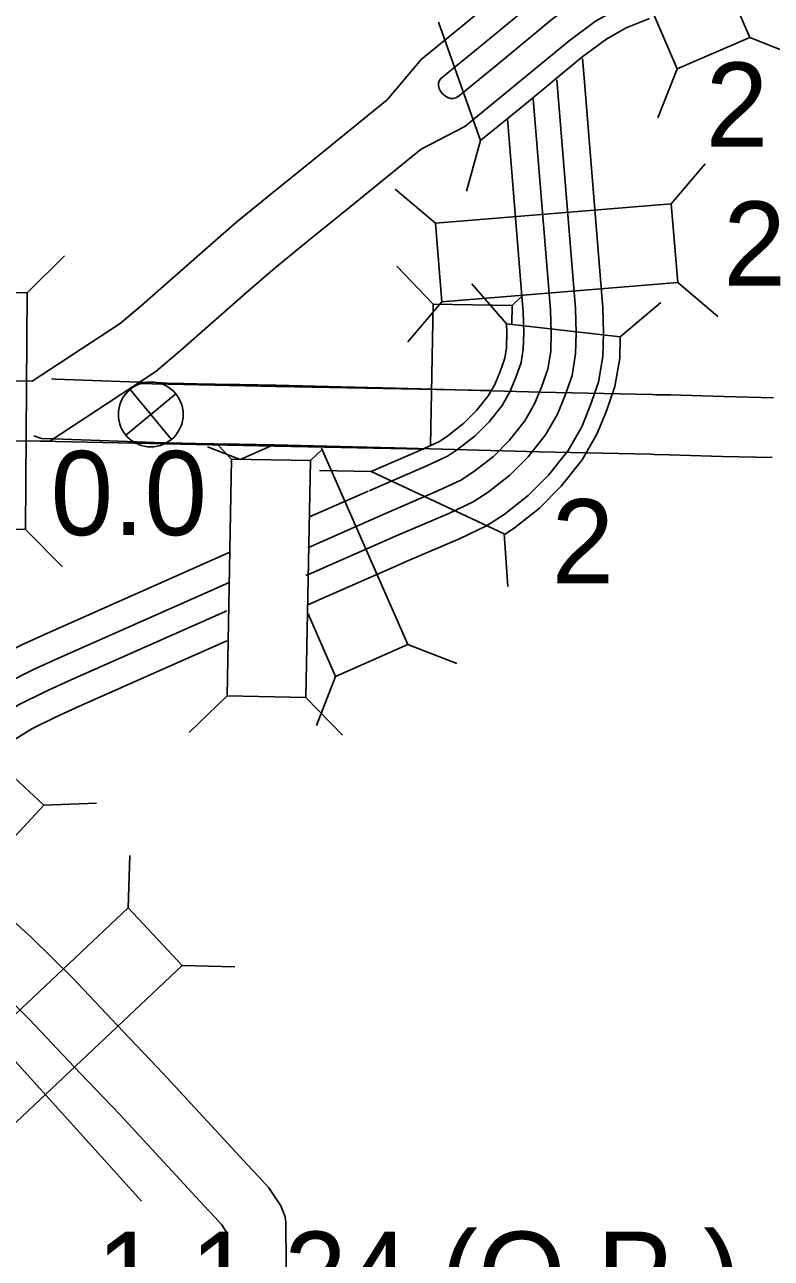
# Model space of a CAD drawing. Extents: x -939622 to -934245, y 1383184 to 1385301.
# Drawn here: x -936404.69 to -936393.44, y 1384599.72 to 1384618.29 of the extents above; entities that cross this region are included whole.
import ezdxf

# ---------------------------------------------------------------- set-up
doc = ezdxf.new("R2010")
doc.units = 0
for name, color, linetype in [('Level 10', 7, 'Continuous'), ('Level 15', 7, 'Continuous'), ('Level 19', 7, 'Continuous'), ('Level 20', 7, 'Continuous'), ('Level 25', 7, 'Continuous'), ('Level 26', 7, 'Continuous')]:
    doc.layers.add(name, color=color, linetype=linetype)

msp = doc.modelspace()

# ---------------------------------------------------------------- linework, layer by layer
at = {"layer": 'Level 10'}
for p, q in [((-936396.919, 1384612.756), (-936399.095, 1384612.817)), ((-936396.944, 1384611.857), (-936399.12, 1384611.918))]:
    msp.add_line(p, q, dxfattribs=at)
for points in [[(-936399.097, 1384612.817), (-936399.723, 1384612.832), (-936400.907, 1384612.863), (-936401.447, 1384612.871), (-936401.821, 1384612.877), (-936401.891, 1384612.878), (-936402.292, 1384612.887), (-936402.547, 1384612.892), (-936402.702, 1384612.899), (-936402.968, 1384612.908), (-936403.807, 1384612.938), (-936404.227, 1384612.952), (-936404.274, 1384612.954), (-936404.266, 1384612.951)], [(-936402.995, 1384612.887), (-936400.903, 1384612.842), (-936397.672, 1384612.78)], [(-936393.41, 1384612.672), (-936394.162, 1384612.689), (-936394.961, 1384612.713), (-936395.176, 1384612.717), (-936395.232, 1384612.719), (-936395.967, 1384612.735), (-936396.921, 1384612.757)], [(-936399.119, 1384611.918), (-936399.745, 1384611.933), (-936400.925, 1384611.963), (-936401.46, 1384611.971), (-936401.835, 1384611.977), (-936401.909, 1384611.978), (-936402.312, 1384611.987), (-936402.575, 1384611.993), (-936402.735, 1384611.999), (-936403, 1384612.008), (-936403.839, 1384612.038), (-936404.258, 1384612.053), (-936404.436, 1384612.059), (-936404.552, 1384612.098)], [(-936404.453, 1384612.018), (-936400.921, 1384611.942), (-936398.682, 1384611.899)], [(-936393.43, 1384611.772), (-936394.186, 1384611.789), (-936394.982, 1384611.814), (-936395.202, 1384611.817), (-936395.26, 1384611.82), (-936395.987, 1384611.835), (-936396.942, 1384611.857)], [(-936400.83, 1384600.505), (-936401.009, 1384600.778), (-936401.168, 1384600.95), (-936401.331, 1384601.123), (-936402.601, 1384602.498), (-936403.205, 1384603.13), (-936403.969, 1384603.94), (-936404.585, 1384604.548), (-936405.293, 1384605.182), (-936406.201, 1384605.924), (-936406.36, 1384606.054)], [(-936401.657, 1384600.125), (-936401.72, 1384600.222), (-936401.826, 1384600.336), (-936401.989, 1384600.51), (-936403.257, 1384601.882), (-936403.858, 1384602.51), (-936404.613, 1384603.311), (-936405.202, 1384603.892), (-936405.879, 1384604.498), (-936406.77, 1384605.228), (-936407.033, 1384605.442)], [(-936400.83, 1384600.505), (-936400.801, 1384600.43), (-936400.766, 1384600.339), (-936400.757, 1384600.262)], [(-936400.851, 1384588.552), (-936400.855, 1384588.625), (-936400.726, 1384596.507), (-936400.757, 1384600.262)], [(-936401.75, 1384588.506), (-936401.756, 1384588.609), (-936401.626, 1384596.511), (-936401.656, 1384600.127)]]:
    msp.add_lwpolyline(points, dxfattribs=at)
at = {"layer": 'Level 15'}
for points in [[(-936398.42, 1384617.477), (-936397.83, 1384617.959), (-936396.976, 1384618.664), (-936396.522, 1384619.001), (-936396.107, 1384619.235), (-936395.184, 1384619.599), (-936394.18, 1384620.033), (-936391.147, 1384621.405), (-936387.048, 1384623.231), (-936384.039, 1384624.587), (-936381.834, 1384625.586), (-936379.396, 1384626.693), (-936377.142, 1384627.69), (-936375.476, 1384628.466), (-936373.359, 1384629.459), (-936371.298, 1384630.427), (-936369.171, 1384631.443), (-936367.666, 1384632.201), (-936365.853, 1384633.102)], [(-936398.164, 1384617.202), (-936397.592, 1384617.669), (-936396.744, 1384618.369), (-936396.317, 1384618.686), (-936395.945, 1384618.896), (-936395.041, 1384619.252), (-936394.028, 1384619.69), (-936390.994, 1384621.062), (-936386.895, 1384622.889), (-936383.884, 1384624.245), (-936381.679, 1384625.245), (-936379.243, 1384626.351), (-936376.987, 1384627.348), (-936375.318, 1384628.126), (-936373.2, 1384629.119), (-936371.138, 1384630.088), (-936369.006, 1384631.107), (-936367.499, 1384631.865), (-936365.686, 1384632.766)], [(-936398.058, 1384616.756), (-936397.33, 1384617.35), (-936396.49, 1384618.044), (-936396.092, 1384618.339), (-936395.767, 1384618.522), (-936394.883, 1384618.871), (-936393.862, 1384619.313), (-936390.825, 1384620.686), (-936386.726, 1384622.512), (-936383.714, 1384623.869), (-936381.509, 1384624.869), (-936379.074, 1384625.975), (-936376.816, 1384626.973), (-936375.143, 1384627.752), (-936373.024, 1384628.746), (-936370.961, 1384629.716), (-936368.824, 1384630.736), (-936367.314, 1384631.496), (-936365.502, 1384632.397)], [(-936398.719, 1384617.765), (-936398.092, 1384618.277), (-936397.23, 1384618.989), (-936396.747, 1384619.348), (-936396.285, 1384619.608), (-936395.835, 1384619.786)], [(-936399.23, 1384617.155), (-936398.719, 1384617.765)], [(-936402.928, 1384614.062), (-936401.889, 1384614.974), (-936401.495, 1384615.318), (-936400.983, 1384615.734), (-936400.36, 1384616.24), (-936399.438, 1384616.985), (-936399.23, 1384617.155)], [(-936398.716, 1384616.412), (-936398.058, 1384616.756)], [(-936402.345, 1384613.376), (-936401.305, 1384614.289), (-936400.915, 1384614.629), (-936400.415, 1384615.036), (-936399.794, 1384615.541), (-936398.871, 1384616.286), (-936398.716, 1384616.412)], [(-936409.262, 1384612.951), (-936404.576, 1384612.919), (-936403.251, 1384613.788), (-936402.928, 1384614.062)], [(-936408.925, 1384612.048), (-936404.31, 1384612.017), (-936402.711, 1384613.066), (-936402.345, 1384613.376)]]:
    msp.add_lwpolyline(points, dxfattribs=at)
msp.add_ellipse((-936398.294, 1384617.341), major_axis=(-0.128, 0.137), ratio=0.733949, start_param=0, end_param=3.141593, dxfattribs=at)
at = {"layer": 'Level 19'}
for points in [[(-936395.991, 1384614.144), (-936396.27, 1384617.547), (-936396.289, 1384617.78)], [(-936400.453, 1384609.993), (-936400.367, 1384610.031), (-936399.106, 1384610.585), (-936398.301, 1384610.931), (-936397.934, 1384611.102), (-936397.708, 1384611.25), (-936397.38, 1384611.508), (-936397.106, 1384611.783), (-936396.844, 1384612.111), (-936396.672, 1384612.414), (-936396.556, 1384612.695), (-936396.446, 1384613.007), (-936396.393, 1384613.331), (-936396.385, 1384613.649), (-936396.394, 1384614.013), (-936396.677, 1384617.456)], [(-936400.426, 1384610.414), (-936399.255, 1384610.929), (-936398.455, 1384611.273), (-936398.118, 1384611.431), (-936397.927, 1384611.555), (-936397.63, 1384611.789), (-936397.386, 1384612.033), (-936397.156, 1384612.322), (-936397.009, 1384612.579), (-936396.907, 1384612.829), (-936396.811, 1384613.101), (-936396.767, 1384613.366), (-936396.76, 1384613.649), (-936396.769, 1384613.993), (-936397.029, 1384617.169)], [(-936397.195, 1384614.141), (-936397.418, 1384616.869)], [(-936399.502, 1384611.271), (-936399.42, 1384611.307), (-936398.623, 1384611.649), (-936398.319, 1384611.792), (-936398.168, 1384611.891), (-936397.904, 1384612.097), (-936397.695, 1384612.308), (-936397.498, 1384612.554), (-936397.381, 1384612.76), (-936397.292, 1384612.975), (-936397.212, 1384613.204), (-936397.179, 1384613.405), (-936397.173, 1384613.649), (-936397.181, 1384613.972), (-936397.195, 1384614.141)], [(-936399.099, 1384610.137), (-936398.941, 1384610.207), (-936398.132, 1384610.554), (-936397.733, 1384610.741), (-936397.467, 1384610.915), (-936397.105, 1384611.199), (-936396.798, 1384611.508), (-936396.502, 1384611.878), (-936396.3, 1384612.233), (-936396.171, 1384612.548), (-936396.045, 1384612.904), (-936395.981, 1384613.292), (-936395.973, 1384613.649), (-936395.982, 1384614.035), (-936395.991, 1384614.143)], [(-936400.397, 1384610.878), (-936399.515, 1384611.266)], [(-936407.557, 1384606.775), (-936406.62, 1384607.781), (-936406.135, 1384608.13), (-936405.629, 1384608.45), (-936405.164, 1384608.737), (-936404.731, 1384608.951), (-936404.346, 1384609.127), (-936401.607, 1384610.342)], [(-936400.435, 1384609.549), (-936400.2, 1384609.653), (-936399.099, 1384610.137)], [(-936407.273, 1384606.474), (-936406.347, 1384607.47), (-936405.904, 1384607.787), (-936405.41, 1384608.1), (-936404.964, 1384608.376), (-936404.554, 1384608.579), (-936404.177, 1384608.751), (-936401.621, 1384609.884)], [(-936407.004, 1384606.213), (-936406.098, 1384607.187), (-936405.694, 1384607.476), (-936405.211, 1384607.783), (-936404.782, 1384608.048), (-936404.392, 1384608.24), (-936404.023, 1384608.409), (-936401.646, 1384609.463)], [(-936406.721, 1384605.911), (-936405.824, 1384606.876), (-936405.464, 1384607.134), (-936404.992, 1384607.433), (-936404.581, 1384607.686), (-936404.215, 1384607.868), (-936403.854, 1384608.033), (-936401.643, 1384609.014)]]:
    msp.add_lwpolyline(points, dxfattribs=at)
at = {"layer": 'Level 20'}
for p, q in [((-936393.77, 1384618.095), (-936395.185, 1384621.366)), ((-936396.275, 1384620.895), (-936394.86, 1384617.623)), ((-936398.456, 1384618.327), (-936397.823, 1384616.544)), ((-936394.86, 1384617.623), (-936393.77, 1384618.095)), ((-936393.77, 1384618.095), (-936393.034, 1384617.803)), ((-936394.86, 1384617.623), (-936395.152, 1384616.887)), ((-936398.035, 1384615.781), (-936397.823, 1384616.544)), ((-936394.951, 1384615.591), (-936394.439, 1384616.195)), ((-936398.503, 1384615.3), (-936399.107, 1384615.812)), ((-936394.951, 1384615.591), (-936398.503, 1384615.3)), ((-936394.854, 1384614.407), (-936394.951, 1384615.591)), ((-936398.503, 1384615.3), (-936398.406, 1384614.116)), ((-936404.651, 1384614.251), (-936404.087, 1384614.808)), ((-936398.535, 1384614.081), (-936399.084, 1384614.652)), ((-936398.406, 1384614.116), (-936394.854, 1384614.407)), ((-936397.953, 1384614.386), (-936397.431, 1384613.785)), ((-936394.854, 1384614.407), (-936394.25, 1384613.895)), ((-936398.406, 1384614.116), (-936398.918, 1384613.512)), ((-936397.347, 1384614.058), (-936397.191, 1384614.208)), ((-936395.11, 1384614.103), (-936395.72, 1384613.588)), ((-936398.535, 1384614.081), (-936398.576, 1384611.952)), ((-936397.347, 1384614.058), (-936398.535, 1384614.081)), ((-936397.353, 1384613.774), (-936397.347, 1384614.058)), ((-936395.72, 1384613.588), (-936397.431, 1384613.785)), ((-936401.441, 1384611.74), (-936401.934, 1384611.932)), ((-936401.573, 1384611.746), (-936401.779, 1384611.96)), ((-936400.985, 1384611.94), (-936401.441, 1384611.74)), ((-936400.385, 1384611.724), (-936400.209, 1384611.893)), ((-936398.919, 1384608.956), (-936400.219, 1384611.912)), ((-936401.573, 1384611.746), (-936401.64, 1384608.183)), ((-936400.385, 1384611.724), (-936401.573, 1384611.746)), ((-936400.452, 1384608.16), (-936400.385, 1384611.724)), ((-936400.248, 1384611.577), (-936399.469, 1384611.563)), ((-936399.469, 1384611.563), (-936397.467, 1384610.62)), ((-936404.675, 1384610.687), (-936404.119, 1384610.124)), ((-936397.41, 1384609.828), (-936397.467, 1384610.62)), ((-936400.421, 1384609.42), (-936400.006, 1384608.477)), ((-936400.006, 1384608.477), (-936398.919, 1384608.956)), ((-936398.919, 1384608.956), (-936398.181, 1384608.668)), ((-936400.006, 1384608.477), (-936400.294, 1384607.739)), ((-936401.64, 1384608.183), (-936402.211, 1384607.633)), ((-936401.64, 1384608.183), (-936400.452, 1384608.16)), ((-936400.452, 1384608.16), (-936399.903, 1384607.59)), ((-936404.398, 1384606.539), (-936403.607, 1384606.568)), ((-936403.129, 1384604.991), (-936403.105, 1384605.782)), ((-936402.314, 1384604.126), (-936401.522, 1384604.102))]:
    msp.add_line(p, q, dxfattribs=at)
for points in [[(-936397.823, 1384616.544), (-936397.132, 1384617.108), (-936396.297, 1384617.797), (-936395.921, 1384618.076), (-936395.632, 1384618.239), (-936395.28, 1384618.378)], [(-936399.469, 1384611.563), (-936398.728, 1384611.882), (-936398.443, 1384612.015), (-936398.316, 1384612.098), (-936398.074, 1384612.288), (-936397.885, 1384612.478), (-936397.709, 1384612.698), (-936397.61, 1384612.872), (-936397.53, 1384613.066), (-936397.46, 1384613.267), (-936397.433, 1384613.429), (-936397.428, 1384613.649), (-936397.431, 1384613.785)], [(-936397.463, 1384610.614), (-936397.319, 1384610.709), (-936396.937, 1384611.009), (-936396.608, 1384611.339), (-936396.291, 1384611.736), (-936396.072, 1384612.122), (-936395.934, 1384612.458), (-936395.799, 1384612.841), (-936395.728, 1384613.268), (-936395.72, 1384613.588)]]:
    msp.add_lwpolyline(points, dxfattribs=at)
for points in [[(-936405.839, 1384614.259), (-936405.863, 1384610.696), (-936404.675, 1384610.687), (-936404.651, 1384614.251)], [(-936407.817, 1384608.097), (-936405.207, 1384605.669), (-936404.398, 1384606.539), (-936407.008, 1384608.967)], [(-936404.908, 1384601.682), (-936402.314, 1384604.126), (-936403.129, 1384604.991), (-936405.723, 1384602.547)]]:
    msp.add_lwpolyline(points, close=True, dxfattribs=at)
at = {"layer": 'Level 25'}
msp.add_line((-936407.156, 1384605.26), (-936402.93, 1384600.577), dxfattribs=at)
at = {"layer": 'Level 26'}
for p, q in [((-936403.166, 1384612.108), (-936402.413, 1384612.731)), ((-936402.478, 1384612.043), (-936403.101, 1384612.796))]:
    msp.add_line(p, q, dxfattribs=at)
msp.add_circle((-936402.789, 1384612.42), 0.488, dxfattribs=at)

# ---------------------------------------------------------------- texts
at = {"layer": 'Level 20'}
for p in [(-936394.433, 1384616.451), (-936394.168, 1384614.359), (-936396.754, 1384609.877)]:
    msp.add_text('2', height=1.267, dxfattribs=at).set_placement(p)
at = {"layer": 'Level 25'}
for s, p in [('0.0', (-936404.298, 1384610.603)), ('1 1.24 (O.P.)', (-936403.608, 1384598.85))]:
    msp.add_text(s, height=1.2672, dxfattribs=at).set_placement(p)

doc.saveas('drawing.dxf')
